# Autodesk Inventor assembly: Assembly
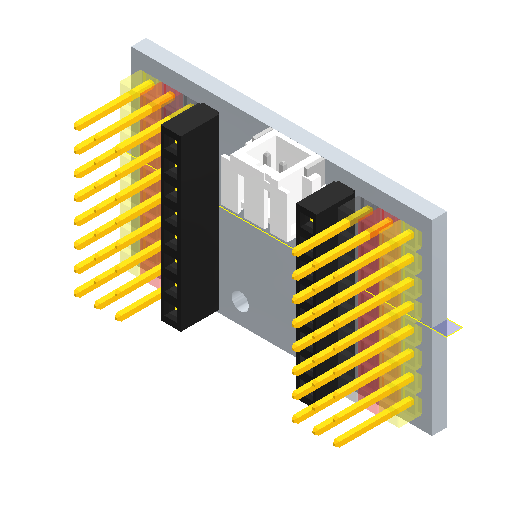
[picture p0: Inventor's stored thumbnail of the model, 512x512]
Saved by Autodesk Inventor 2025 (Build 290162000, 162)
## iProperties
Created: 2024-08
Part Number: Assembly
Description: FreeCAD Model
Document SubType Name: Assembly
Designer: R5800u
Authority: Unknown
Sending System: Ondsel
Preprocessor: Open CASCADE STEP processor 7.7
Title: Open CASCADE Shape Model
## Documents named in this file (7)
- C:\Users\R5800u\Desktop\drone_v2\ESP32-C3 Super Mini breakout expansion board module -Assembly.iam
- C:\Users\R5800u\Desktop\drone_v2\pcb.ipt
- C:\Users\R5800u\Desktop\drone_v2\pinheaderyellow.iam
- C:\Users\R5800u\Desktop\drone_v2\pinheader8Red.iam
- C:\Users\R5800u\Desktop\drone_v2\pinheader8Black.iam
- C:\Users\R5800u\Desktop\drone_v2\JST - PH - SMD (R) - 2Pin - 2.00mm.ipt
- C:\Users\R5800u\Desktop\drone_v2\8er Pin Header Female_1.ipt
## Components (10 placed, 10 different names)
1. 1
2. 20 [sub-assembly]
3. 39 [sub-assembly]
4. 58 [sub-assembly]
5. 59
6. 60 [sub-assembly]
7. 61 [sub-assembly]
8. 62 [sub-assembly]
9. 63
10. 64
